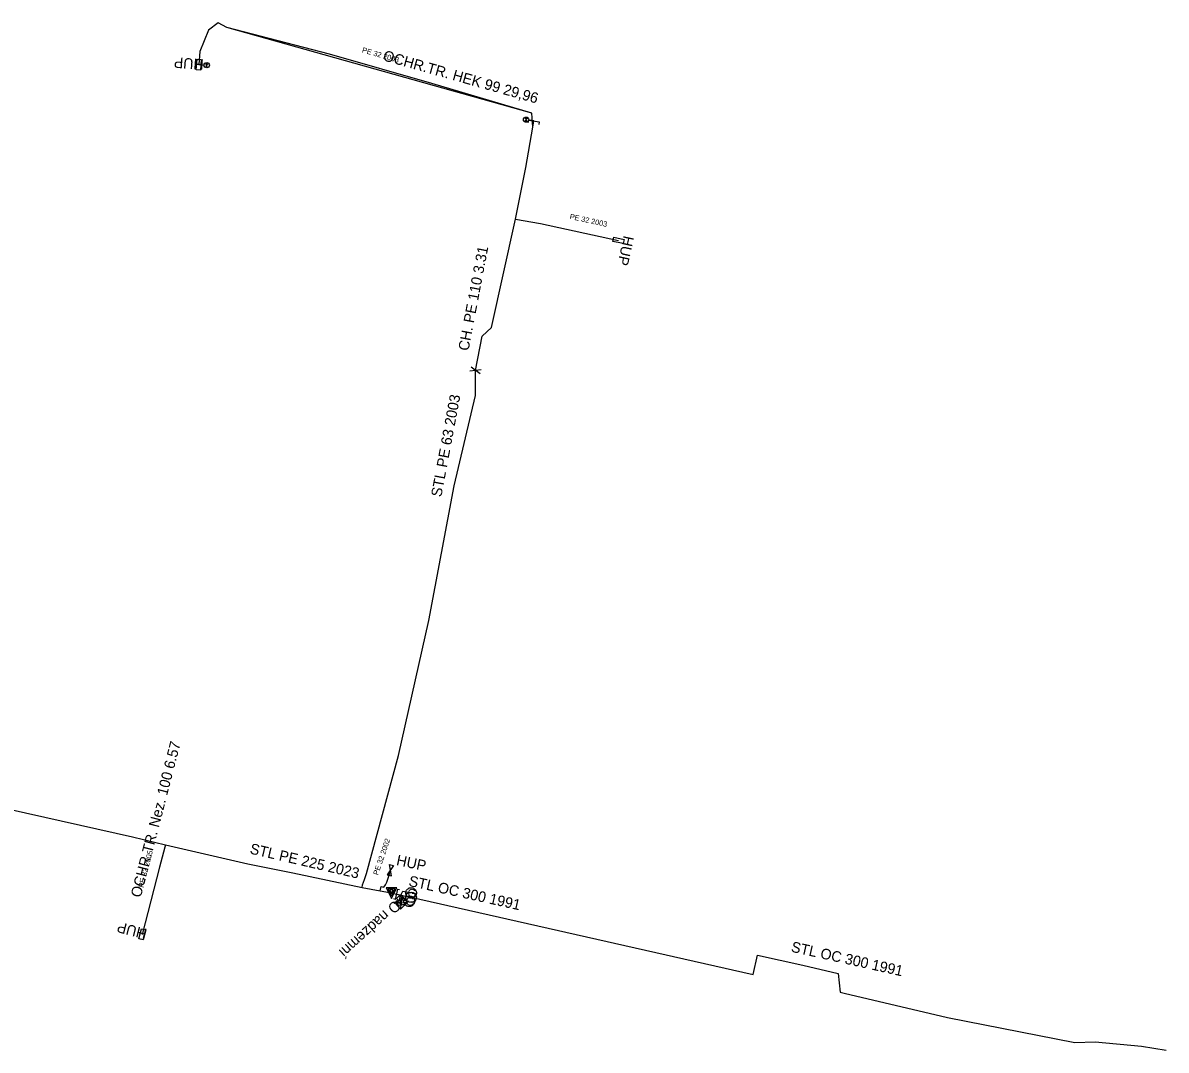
# Model space of a CAD drawing. Extents: x -745298 to -745026, y -1052719 to -1052281.
# Drawn here: x -745152.9 to -745044.8, y -1052554 to -1052456.9 of the extents above; entities that cross this region are included whole.
import ezdxf

# ---------------------------------------------------------------- set-up
doc = ezdxf.new("R2010")
doc.units = 0
for name, color, linetype in [('Kabel PKO', 7, 'Continuous'), ('ST OP Chráni_ka - provoz', 7, 'Continuous'), ('ST Úsek p_ípojky - provoz', 7, 'Continuous'), ('ST Úsek plynovodu - provoz', 7, 'Continuous'), ('ST_HUP_22_23_popis', 7, 'Continuous'), ('ST_HUP_24_popis', 7, 'Continuous'), ('Vrstva 1', 7, 'Continuous'), ('Vrstva 5', 7, 'Continuous'), ('Za_ízení PKO - provoz_popis', 7, 'Continuous')]:
    doc.layers.add(name, color=color, linetype=linetype)

msp = doc.modelspace()

# ---------------------------------------------------------------- linework, layer by layer
at = {"layer": 'Kabel PKO'}
for points in [[(-745117.16, -1052539.38), (-745116.98, -1052539.01), (-745116.2, -1052539.18)], [(-745117.22, -1052539.37), (-745117.57, -1052539.69)], [(-745117.16, -1052539.38), (-745117.15, -1052539.79), (-745116.37, -1052539.96)]]:
    msp.add_lwpolyline(points, dxfattribs=at)
at = {"layer": 'ST OP Chráni_ka - provoz'}
for points in [[(-745104.78, -1052465.42), (-745133.62, -1052457.3)], [(-745110.1, -1052489.76), (-745109.48, -1052486.51)], [(-745198.12, -1052521.42), (-745142.56, -1052533.88)], [(-745139.98, -1052536.74), (-745141.62, -1052543.1)]]:
    msp.add_lwpolyline(points, dxfattribs=at)
at = {"layer": 'ST Úsek p_ípojky - provoz'}
for points in [[(-745104.68, -1052466.74), (-745104.78, -1052465.42), (-745114.24, -1052462.6), (-745123.9, -1052459.82), (-745133.62, -1052457.3), (-745134.45, -1052456.87), (-745135.35, -1052457.57), (-745136.19, -1052459.59), (-745136.28, -1052460.82)], [(-745106.33, -1052475.44), (-745103.95, -1052475.84), (-745096.58, -1052477.45)], [(-745139.5, -1052534.84), (-745139.98, -1052536.74), (-745141.62, -1052543.1)], [(-745139.44, -1052534.62), (-745139.5, -1052534.84)], [(-745118.78, -1052538.63), (-745118.62, -1052538.41), (-745118.49, -1052538.16), (-745118.29, -1052537.58), (-745118.15, -1052537.03)], [(-745119.13, -1052538.99), (-745119.03, -1052538.56), (-745118.78, -1052538.63)]]:
    msp.add_lwpolyline(points, dxfattribs=at)
at = {"layer": 'ST Úsek plynovodu - provoz'}
for points in [[(-745120.62, -1052537.9), (-745120.42, -1052537.35), (-745117.38, -1052526.18), (-745114.52, -1052513.42), (-745112.12, -1052500.67), (-745110.1, -1052492.13), (-745110.1, -1052489.76), (-745109.48, -1052486.51), (-745108.6, -1052485.68), (-745106.33, -1052475.44), (-745105.35, -1052470.56), (-745104.68, -1052466.74), (-745104.58, -1052466.15)], [(-745211.7, -1052522.27), (-745210.97, -1052522.13), (-745202.36, -1052520.72), (-745200.88, -1052520.93), (-745198.12, -1052521.42), (-745142.56, -1052533.88)], [(-745142.56, -1052533.88), (-745139.44, -1052534.62), (-745131.65, -1052536.43), (-745127.39, -1052537.29), (-745120.84, -1052538.65)], [(-745120.84, -1052538.65), (-745120.79, -1052538.4), (-745120.62, -1052537.9)], [(-745120.84, -1052538.65), (-745119.13, -1052538.99), (-745118.24, -1052539.15), (-745118.05, -1052539.19)], [(-745118.05, -1052539.19), (-745117.85, -1052539.23), (-745117.56, -1052539.3)], [(-745117.56, -1052539.3), (-745117.22, -1052539.37)], [(-745117.22, -1052539.37), (-745116.88, -1052539.44), (-745116.2, -1052539.59)], [(-745116.2, -1052539.59), (-745115.38, -1052539.77), (-745083.83, -1052546.88), (-745083.43, -1052545.06), (-745079.15, -1052546.01), (-745075.79, -1052546.8), (-745075.6, -1052548.57), (-745075.24, -1052548.65), (-745065.45, -1052550.96), (-745053.42, -1052553.33), (-745051.48, -1052553.26), (-745047.12, -1052553.67), (-745044.78, -1052554.05)]]:
    msp.add_lwpolyline(points, dxfattribs=at)
at = {"layer": 'Vrstva 1'}
for p, q in [((-745136.28, -1052460.82), (-745135.78, -1052460.86)), ((-745104.58, -1052466.15), (-745105.08, -1052466.07)), ((-745109.67, -1052490.08), (-745110.53, -1052489.44)), ((-745109.57, -1052489.7), (-745110.63, -1052489.82)), ((-745117.67, -1052539.79), (-745117.45, -1052538.81)), ((-745117.45, -1052538.81), (-745117.3, -1052538.85)), ((-745117.67, -1052539.79), (-745117.82, -1052539.75)), ((-745117.22, -1052539.37), (-745117.32, -1052539.86))]:
    msp.add_line(p, q, dxfattribs=at)
for points in [[(-745136.12, -1052461.33), (-745136.52, -1052461.3), (-745136.44, -1052460.31), (-745136.04, -1052460.34)], [(-745096.05, -1052477.36), (-745096.13, -1052477.75), (-745097.11, -1052477.54), (-745097.03, -1052477.15)], [(-745117.55, -1052538.69), (-745118.55, -1052538.69), (-745118.05, -1052539.69)], [(-745118.39, -1052538.79), (-745118.05, -1052539.47), (-745117.71, -1052538.79)], [(-745118.05, -1052539.24), (-745117.88, -1052538.89), (-745118.23, -1052538.89)], [(-745116.26, -1052539.5), (-745116.11, -1052539.54), (-745116.14, -1052539.68), (-745116.29, -1052539.64)], [(-745141.55, -1052543.63), (-745141.94, -1052543.53), (-745141.69, -1052542.57), (-745141.3, -1052542.67)]]:
    msp.add_lwpolyline(points, close=True, dxfattribs=at)
for points in [[(-745105.11, -1052466.31), (-745105.07, -1052466.07), (-745104.09, -1052466.23), (-745104.13, -1052466.48)], [(-745118.24, -1052536.5), (-745117.85, -1052536.58), (-745118.45, -1052537.48), (-745118.06, -1052537.56), (-745118.24, -1052536.5)]]:
    msp.add_lwpolyline(points, dxfattribs=at)
for centre, radius in [((-745135.53, -1052460.87), 0.249), ((-745135.55, -1052460.97), 0.0614), ((-745135.53, -1052460.77), 0.0614), ((-745105.32, -1052466.03), 0.249), ((-745105.33, -1052466.13), 0.0614), ((-745105.29, -1052465.93), 0.0614), ((-745116.2, -1052539.59), 0.5), ((-745117.37, -1052540.11), 0.249), ((-745117.47, -1052540.07), 0.0614), ((-745117.27, -1052540.11), 0.0614)]:
    msp.add_circle(centre, radius, dxfattribs=at)
at = {"layer": 'Vrstva 5'}
for p, q in [((-745117.8, -1052540.1), (-745117.73, -1052540.17)), ((-745117.8, -1052540.13), (-745117.76, -1052540.17)), ((-745117.57, -1052539.69), (-745117.37, -1052539.91)), ((-745117.19, -1052540.7), (-745117, -1052539.57))]:
    msp.add_line(p, q, dxfattribs=at)
for points in [[(-745116.22, -1052538.68), (-745116.17, -1052538.68), (-745116.12, -1052538.69), (-745116.08, -1052538.7), (-745116.03, -1052538.71), (-745115.98, -1052538.73), (-745115.94, -1052538.75), (-745115.9, -1052538.78), (-745115.86, -1052538.81), (-745115.83, -1052538.85), (-745115.79, -1052538.88), (-745115.77, -1052538.93), (-745115.74, -1052538.97), (-745115.73, -1052539.01), (-745115.71, -1052539.06), (-745115.7, -1052539.11), (-745115.7, -1052539.16), (-745115.7, -1052539.21), (-745115.7, -1052539.26), (-745115.71, -1052539.3), (-745115.73, -1052539.35), (-745115.74, -1052539.4), (-745115.77, -1052539.44), (-745115.79, -1052539.48), (-745115.83, -1052539.52), (-745115.86, -1052539.55), (-745115.9, -1052539.58), (-745115.94, -1052539.61), (-745115.98, -1052539.64), (-745116.03, -1052539.65), (-745116.08, -1052539.67), (-745116.12, -1052539.68), (-745116.17, -1052539.68), (-745116.22, -1052539.68), (-745116.27, -1052539.68), (-745116.32, -1052539.67), (-745116.37, -1052539.65), (-745116.41, -1052539.64), (-745116.45, -1052539.61), (-745116.49, -1052539.58), (-745116.53, -1052539.55), (-745116.57, -1052539.52), (-745116.6, -1052539.48), (-745116.63, -1052539.44), (-745116.65, -1052539.4), (-745116.67, -1052539.35), (-745116.68, -1052539.3), (-745116.69, -1052539.26), (-745116.7, -1052539.21), (-745116.7, -1052539.16), (-745116.69, -1052539.11), (-745116.68, -1052539.06), (-745116.67, -1052539.01), (-745116.65, -1052538.97), (-745116.63, -1052538.93), (-745116.6, -1052538.88), (-745116.57, -1052538.85), (-745116.53, -1052538.81), (-745116.49, -1052538.78), (-745116.45, -1052538.75), (-745116.41, -1052538.73), (-745116.37, -1052538.71), (-745116.32, -1052538.7), (-745116.27, -1052538.69)], [(-745116.4, -1052539.46), (-745116.35, -1052539.46), (-745116.3, -1052539.47), (-745116.25, -1052539.48), (-745116.2, -1052539.49), (-745116.16, -1052539.51), (-745116.11, -1052539.53), (-745116.07, -1052539.56), (-745116.04, -1052539.59), (-745116, -1052539.63), (-745115.97, -1052539.67), (-745115.94, -1052539.71), (-745115.92, -1052539.75), (-745115.9, -1052539.79), (-745115.89, -1052539.84), (-745115.88, -1052539.89), (-745115.87, -1052539.94), (-745115.87, -1052539.99), (-745115.88, -1052540.04), (-745115.89, -1052540.08), (-745115.9, -1052540.13), (-745115.92, -1052540.18), (-745115.94, -1052540.22), (-745115.97, -1052540.26), (-745116, -1052540.3), (-745116.04, -1052540.33), (-745116.07, -1052540.36), (-745116.11, -1052540.39), (-745116.16, -1052540.42), (-745116.2, -1052540.43), (-745116.25, -1052540.45), (-745116.3, -1052540.46), (-745116.35, -1052540.46), (-745116.4, -1052540.46), (-745116.45, -1052540.46), (-745116.49, -1052540.45), (-745116.54, -1052540.43), (-745116.59, -1052540.42), (-745116.63, -1052540.39), (-745116.67, -1052540.36), (-745116.71, -1052540.33), (-745116.74, -1052540.3), (-745116.77, -1052540.26), (-745116.8, -1052540.22), (-745116.82, -1052540.18), (-745116.84, -1052540.13), (-745116.86, -1052540.08), (-745116.87, -1052540.04), (-745116.87, -1052539.99), (-745116.87, -1052539.94), (-745116.87, -1052539.89), (-745116.86, -1052539.84), (-745116.84, -1052539.79), (-745116.82, -1052539.75), (-745116.8, -1052539.71), (-745116.77, -1052539.67), (-745116.74, -1052539.63), (-745116.71, -1052539.59), (-745116.67, -1052539.56), (-745116.63, -1052539.53), (-745116.59, -1052539.51), (-745116.54, -1052539.49), (-745116.49, -1052539.48), (-745116.45, -1052539.47)]]:
    msp.add_lwpolyline(points, close=True, dxfattribs=at)
for points in [[(-745117.51, -1052540.04), (-745117.58, -1052539.97), (-745117.8, -1052540.17)], [(-745116.53, -1052540.09), (-745117, -1052539.57), (-745117.66, -1052540.18), (-745117.19, -1052540.7), (-745116.53, -1052540.09), (-745117.66, -1052540.18)]]:
    msp.add_lwpolyline(points, dxfattribs=at)

# ---------------------------------------------------------------- texts
at = {"layer": 'ST OP Chráni_ka - provoz'}
for s, rotation, p in [('OCHR.TR. HEK 99 29,96', 344.2734, (-745118.93, -1052460.4)), ('CH. PE 110 3.31', 79.1995, (-745110.77, -1052487.95)), ('OCHR.TR. Nez. 100 6.57', 75.5406, (-745141.77, -1052539.67))]:
    msp.add_text(s, height=1, rotation=rotation, dxfattribs=at).set_placement(p)
at = {"layer": 'ST Úsek p_ípojky - provoz'}
for s, rotation, p in [('PE 32 2003', 343.945, (-745120.88, -1052459.65)), ('PE 32 2003', 347.6846, (-745101.23, -1052475.41)), ('PE 32 2002', 71.0296, (-745119.33, -1052537.54)), ('PE 32 2005', 75.5406, (-745141.52, -1052538.72))]:
    msp.add_text(s, height=0.5, rotation=rotation, dxfattribs=at).set_placement(p)
at = {"layer": 'ST Úsek plynovodu - provoz'}
for s, rotation, p in [('STL PE 63 2003', 79.3397, (-745113.34, -1052501.77)), ('STL PE 225 2023', 346.9195, (-745131.51, -1052535.44)), ('STL OC 300 1991', 347.5604, (-745116.49, -1052538.5)), ('STL OC 300 1991', 347.474, (-745080.31, -1052544.73))]:
    msp.add_text(s, height=1, rotation=rotation, dxfattribs=at).set_placement(p)
at = {"layer": 'ST_HUP_22_23_popis'}
for rotation, p in [(175.82, (-745135.78, -1052460.32)), (257.68, (-745096.08, -1052476.95)), (165.54, (-745141.12, -1052542.6))]:
    msp.add_text('HUP', height=1, rotation=rotation, dxfattribs=at).set_placement(p)
at = {"layer": 'ST_HUP_24_popis'}
msp.add_text('HUP', height=1, rotation=348.11, dxfattribs=at).set_placement((-745117.65, -1052536.53))
at = {"layer": 'Vrstva 5'}
for p in [(-745116.53, -1052539.59), (-745116.71, -1052540.37)]:
    msp.add_text('G', height=0.784, dxfattribs=at).set_placement(p)
at = {"layer": 'Za_ízení PKO - provoz_popis'}
msp.add_text('PO nadzemní', height=1, rotation=222.18, dxfattribs=at).set_placement((-745117.07, -1052539.19))

doc.saveas('drawing.dxf')
